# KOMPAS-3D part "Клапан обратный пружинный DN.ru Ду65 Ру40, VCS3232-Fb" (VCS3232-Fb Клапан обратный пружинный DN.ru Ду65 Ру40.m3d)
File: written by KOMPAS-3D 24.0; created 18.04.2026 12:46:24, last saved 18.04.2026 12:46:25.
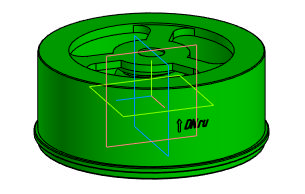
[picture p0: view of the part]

Document properties: Автор: 712; Полное имя файла: C:\Users\712\Desktop\Новая папка (4)\VCS3232-Fb Клапан обратный пружинный DN.ru Ду65 Ру40.m3d

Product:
- Component: Пружина 1086-0916 ГОСТ 18793-80  | qty 1  | additional columns: 3953604318-4147491677-0; Деталь; Пользователь Windows; c; Шероховатость не задана; Да; Сталь 10  ГОСТ 1050-88; source file: Деталь_4.m3d
- Body: Тело 1  | qty 1
    Масса: 1.486414
- Part/product: Клапан обратный пружинный DN.ru Ду65 Ру40  | designation VCS3232-Fb
    Масса: 1.76
    Раздел спецификации: Прочие изделия
    Примечание: D100-03905
    additional columns: 071bd168-1a06-425c-849c-e99e84a96128; Деталь; 712; c; Шероховатость не задана; Да

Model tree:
1. Операция без истории:2

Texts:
  VCS3232-Fb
